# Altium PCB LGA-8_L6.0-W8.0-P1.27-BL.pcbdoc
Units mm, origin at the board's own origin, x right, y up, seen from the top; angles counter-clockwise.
Board outline 18.85 x 22.43 mm, 2 copper layers (Top Layer, Bottom Layer), stack 0 mm thick; 1 components, 0 nets, 8 pads, 0 vias.
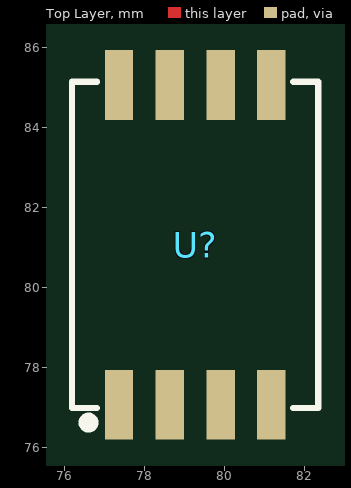
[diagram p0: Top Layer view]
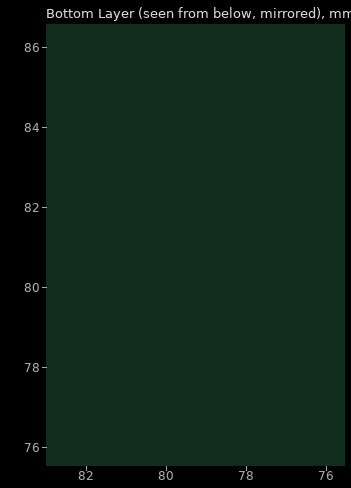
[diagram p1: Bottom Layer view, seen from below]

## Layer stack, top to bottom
Top Layer: signal copper (thickness not stored)
Bottom Layer: signal copper (thickness not stored)

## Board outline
88.702,69.85 69.85,69.85 69.85,92.281 88.702,92.281

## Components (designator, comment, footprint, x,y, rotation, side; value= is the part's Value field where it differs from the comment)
U? "" LGA-8_L6.0-W8.0-P1.27-BL 79.276,81.066 r0 top

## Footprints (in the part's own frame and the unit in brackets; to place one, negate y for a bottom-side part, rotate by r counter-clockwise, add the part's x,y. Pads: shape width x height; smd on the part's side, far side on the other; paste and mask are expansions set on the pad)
LGA-8_L6.0-W8.0-P1.27-BL [mil]
  rect 28x68.53 smd: 1(-75,-157.3) 2(-25,-157.3) 3(25,-157.3) 4(75,-157.3) 5(75,157.29) 6(25,157.29) 7(-25,157.29) 8(-75,157.29)
  silkscreen extent -121,-180 121,160

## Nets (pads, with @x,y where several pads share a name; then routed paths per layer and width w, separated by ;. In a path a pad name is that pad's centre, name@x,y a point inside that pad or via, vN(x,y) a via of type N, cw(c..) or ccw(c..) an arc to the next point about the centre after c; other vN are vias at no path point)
pads on no net: U?.1 U?.2 U?.3 U?.4 U?.5 U?.6 U?.7 U?.8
